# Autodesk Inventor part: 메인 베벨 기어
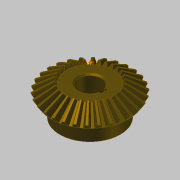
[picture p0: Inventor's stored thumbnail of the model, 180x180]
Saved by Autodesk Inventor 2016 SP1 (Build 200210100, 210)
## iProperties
Created: 2016-04
Part Number: 메인 베벨 기어
Material: 강철, 탄소
Document SubType Name: Modeling
Designer: mdu
Categories: <?xml version="1.0" encoding="UTF-16"?> <MemberInstance><Categories><FamilyTemplate><FamilyTemplateParameter ValueType="xs:double" Id="1" ObjectReferenceKey="da
Mass: 269.926 g
Surface Area: 108.837 cm^2
Volume: 34.2981 cm^3
Density: 7.87 g/cm^3
Appearance: 얼룩무늬
CustomPartVersion: 1
Author: mdu
Revision Number: 1
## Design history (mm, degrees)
node "맨 위 점"
node "메쉬 평면2"
sketch "톱니 본체 스케치"
  geometry: L1 (0, 0)-(28.669, -21.997); L2 (28.669, -21.997)-(31.109, -18.336); L3 (31.109, -18.336)-(0, 0); L4 (30, -20)-(0, 0); L5 (17.219, -13.212)-(18.685, -11.013); L6 (28.669, -21.997)-(17.219, -13.212); L7 (31.109, -18.336)-(18.685, -11.013); L8 (0, -39.387)-(0, 6.564) reference; L9 (0, -20)-(31.109, -20)
  constraints: 16 end point, 4 point on line, 3 perpendicular, 2 collinear, 1 horizontal alignment, 1 vertical alignment
  dimensions: "d0" = 60 diameter of L4.start L8 (= da_de); "d1" = 57.33744 diameter of L1.end L8 (= da_dfe); "d2" = 62.2188 diameter of L2.end L8 (= da_dae); "d3" = 14.4 distance between parallel lines of L2 L5 (= da_b); "d4" = 18.3359 vertical distance of L2.end L1.start (= da_ve)
revolve "톱니 본체" sketch "톱니 본체 스케치" stored, may be unused: angle "d5" = 90 deg
node "시작점"
node "톱니 평면"
sketch "시작 스케치"
  geometry: L1 (0, -23.505)-(0, 10.645) reference; L2 (-0.709, -2.928)-(0.709, -2.928); A1 r 19.188 centre (-19.457, -7.014) between (-0.709, -2.928) and (-3.232, 3.229); A2 r 19.188 centre (19.457, -7.014) between (3.232, 3.229) and (0.709, -2.928); A3 r 57.403 centre (0, -54.083) between (3.232, 3.229) and (-3.232, 3.229); 1 further point
  constraints: 6 point on circle, 3 centre point, 3 symmetric about line, 2 end point, 1 coincident, 1 perpendicular, 1 other
  dimensions: "d7" = 19.18795 radius of A1 (= fd_rr); "d8" = 19.45712 horizontal distance of point (0, -54.083) A1.centre (= fd_x); "d9" = 47.06905 vertical distance of point (0, -54.083) A1.centre (= fd_y); "d57" = 57.40327 radius of A3 (= 0.5 x fd_dva + 0.3 x da_he); "d58" = 51.15527 distance from line of A3.centre L2 (= 0.5 x fd_dva - 1.12 x da_he)
node "끝점"
  node "끝 평면"
sketch "3D 스케치 오른쪽"
  node "Helical Curve Right" dims "d65" = 229.90621 (computed from da_dm, da_delta, da_beta), "d66" = 31.5, "d67" = 60 (= da_de), "d68" = -9.82794 (= -da_delta), "d69" = 8.10972 (computed from fd_loft, da_delta)
node "끝 평면 오른쪽"
sketch "끝 스케치 오른쪽"
  geometry: L1 (0, -41.54)-(0, 13.178) reference; L2 (-0.422, -1.69)-(0.422, -1.69); A1 r 11.427 centre (-11.587, -4.123) between (-0.422, -1.69) and (-1.925, 1.977); A2 r 11.427 centre (11.587, -4.123) between (1.925, 1.977) and (0.422, -1.69); A3 r 34.184 centre (0, -32.153) between (1.925, 1.977) and (-1.925, 1.977); 1 further point
  constraints: 6 point on circle, 3 centre point, 3 symmetric about line, 2 end point, 1 coincident, 1 perpendicular, 1 other
  dimensions: "d70" = 11.58699 horizontal distance of A3.centre A1.centre (computed from fd_x, fd_ratio); "d71" = 28.03028 vertical distance of point (0, -32.153) A1.centre (computed from fd_y, fd_ratio); "d72" = 11.4267 radius of A1 (computed from fd_rr, fd_ratio); "d73" = 30.46369 distance from line of point (0, -32.153) L2 (computed from d58, fd_ratio); "d74" = 34.18446 radius of A3 (computed from d57, fd_ratio)
feature "로프트 오른쪽" sketch "끝 스케치 오른쪽" dims "d75" = 0, "d77" = 0, "d79" = 0, "d80" = 90 deg, "d85" = 20, "d92" = 90 deg, "d93" = 90 deg, "da_teethtype" = 0 [user parameter]
sketch "3D 스케치 왼쪽"
  node "Helical Curve Left" dims "d26" = 229.90621 (computed from da_dm, da_delta, da_beta), "d27" = 8.10972 (computed from fd_loft, da_delta), "d28" = 60 (= da_de), "d29" = -9.82794 (= -da_delta)
node "끝 평면 왼쪽"
sketch "끝 스케치 왼쪽" dims "d56" = 10.3728 (derived)
  geometry: L1 (0, -43.753)-(0, 15.405) reference; L2 (-0.422, -1.678)-(0.422, -1.678); A1 r 11.427 centre (-11.587, -4.111) between (-0.422, -1.678) and (-1.925, 1.988); A2 r 11.427 centre (11.587, -4.111) between (1.925, 1.988) and (0.422, -1.678); A3 r 34.184 centre (0, -32.142) between (1.925, 1.988) and (-1.925, 1.988); 2 further points; 1 other entity
  constraints: 6 point on circle, 3 centre point, 3 symmetric about line, 2 end point, 1 coincident, 2 other
  dimensions: "d30" = 11.4267 radius of A1 (computed from fd_rr, fd_ratio); "d31" = 11.58699 horizontal distance of point (0, -32.142) A1.centre (computed from fd_x, fd_ratio); "d32" = 28.03028 vertical distance of A1.centre point (0, -32.142) (computed from fd_y, fd_ratio); "d61" = 34.18446 radius of A3 (computed from d57, fd_ratio); "d62" = 30.46369 distance from line of point (0, -32.142) L2 (computed from d58, fd_ratio)
feature "로프트 왼쪽" sketch "끝 스케치 왼쪽" dims "d35" = 0, "d37" = 0, "d39" = 0, "d40" = 90 deg, "d84" = 10, "d90" = 90 deg, "d91" = 90 deg, "da_teethtype" = 0 [user parameter]
sketch "본체 스케치"
  geometry: L1 (0, -35.038)-(0, -19.531) reference; L2 (28.669, -21.997)-(17.219, -13.212) reference; L3 (17.219, -13.212)-(0, -13.212); L4 (28.669, -21.997)-(0, -21.997)
  constraints: 4 end point, 2 perpendicular, 2 point on line
revolve "본체 고정" sketch "본체 스케치" stored, may be unused: angle "d46" = 90 deg
feature "피치 지름" dims angle "d47" = 90 deg
sketch "스케치8"
  geometry: C1 r 22.5 at (0, 0); 1 further point
  constraints: 1 centre point, 1 coincident
  dimensions: "d94" = 45 diameter of C1
extrude "돌출1" join sketch "스케치8" distance "d95" = 13; taper "d96" = 0 deg
sketch "스케치9"
  geometry: 1 further point
hole "구멍1" sketch "스케치9" at (0, 0) diameter "d97" = 17; stored, may be unused: countersink angle "d101" = 90 deg, drill point angle "d103" = 118 deg; dims "d98" = 6, "d99" = 4, "d100" = 2, "d102" = 8
sketch "스케치10"
  geometry: L1 (8.124, 2.5)-(10.8, 2.5); L2 (10.8, 2.5)-(10.8, -2.5); L3 (10.8, -2.5)-(8.124, -2.5); A1 r 8.5 centre (0, 0) between (8.124, 2.5) and (8.124, -2.5) reference; 1 further point
  constraints: 6 end point, 2 parallel, 2 point on circle, 1 horizontal, 1 perpendicular
  dimensions: "d104" = 5 distance of L1.end L2.end; "d112" = 19.3 dimension on A1 L2
extrude "돌출2" cut sketch "스케치10" stored distance "d106" = 10; taper "d107" = 0 deg
chamfer "모따기1" distance "d108" = 1; stored, may be unused: second distance "d109" = 2, angle "d110" = 45 deg
fillet "모깎기1" dims "d111" = 2
body "Solid1"
feature "로프트" dims "d17" = 0, "d18" = 90 deg, "d19" = 0, "d20" = 90 deg, "d89" = 0, "da_teethtype" = 0 [user parameter]
pattern_circular "원형 패턴" dims angle "d22" = 360 deg, "d88" = 0, "da_teethtype" = 0 [user parameter]
pattern_circular "원형 패턴 오른쪽" dims angle "d82" = 360 deg, "da_teethtype" = 0 [user parameter]
pattern_circular "원형 패턴 왼쪽" dims angle "d42" = 360 deg, "da_teethtype" = 0 [user parameter]
sketch "끝 스케치"
  geometry: L1 (0, -15.359)-(0, 6.983) reference; L2 (-0.422, -1.69)-(0.422, -1.69); A1 r 11.427 centre (-11.587, -4.123) between (-0.422, -1.69) and (-1.925, 1.977); A2 r 11.427 centre (11.587, -4.123) between (1.925, 1.977) and (0.422, -1.69); A3 r 34.184 centre (0, -32.153) between (1.925, 1.977) and (-1.925, 1.977); 1 further point
  constraints: 6 point on circle, 3 centre point, 3 symmetric about line, 2 end point, 1 coincident, 1 other
  dimensions: "d12" = 11.4267 radius of A1 (computed from fd_rr, fd_ratio); "d15" = 11.58699 horizontal distance of A1.centre point (0, -32.153) (computed from fd_x, fd_ratio); "d16" = 28.03028 vertical distance of A1.centre point (0, -32.153) (computed from fd_y, fd_ratio); "d59" = 34.18446 radius of A3 (computed from d57, fd_ratio); "d60" = 30.46369 distance from line of A3.centre L2 (computed from d58, fd_ratio)
sketch "Sketch6"
  geometry: L1 (30, -20)-(0, 0) reference; L2 (0, -37.8)-(0, 6.3) reference
body "Srf1"
other parameters: "da_b" = 14.4 [user parameter; used in 2 equation terms], "da_de" = 60 [user parameter; used in 4 equation terms], "da_dae" = 62.2188 [user parameter; used in 2 equation terms], "da_dfe" = 57.33744 [user parameter; used in 1 equation term], "da_le" = 36.05551 [user parameter; used in 1 equation term], "da_omega" = 90 deg [user parameter; used in 1 equation term], "da_beta" = 0 [user parameter; used in 2 equation terms], "da_delta" = 9.82794 [user parameter; used in 8 equation terms], "da_alpha" = 20 deg [user parameter; used in 2 equation terms], "da_he" = 4.4 [user parameter; used in 4 equation terms], "da_ve" = 18.3359 [user parameter; used in 1 equation term], "fd_dv" = 108.16654 (computed from da_de, da_delta) [user parameter; used in 1 equation term], "fd_dva" = 112.16654 (computed from da_dae, da_delta) [user parameter; used in 3 equation terms], "fd_dvb" = 101.6433 (computed from fd_dv, da_alpha) [user parameter; used in 2 equation terms], "da_zv" = 540.83269 [user parameter; used in 1 equation term], "fd_loft" = 14.62 (= da_b + 0.05 x da_he) [user parameter; used in 4 equation terms], "fd_ratio" = 5.95514 (computed from da_le, fd_loft) [user parameter; used in 15 equation terms], "fd_rr" = 19.18795 (computed from fd_dd, fd_dvb) [user parameter; used in 6 equation terms], "fd_angle" = 0.29367 (computed from da_zv) [user parameter; used in 4 equation terms], "fd_x1" = 1.58802 (computed from da_dvw, fd_angle) [user parameter; used in 1 equation term], "fd_y1" = 54.05995 (computed from da_dvw, fd_angle) [user parameter; used in 1 equation term], "fd_x2" = 17.8691 (computed from fd_rr, fd_angle2, fd_angle) [user parameter; used in 1 equation term], "fd_y2" = 6.9909 (computed from fd_rr, fd_angle2, fd_angle) [user parameter; used in 1 equation term], "fd_x" = 19.45712 (= fd_x1 + fd_x2) [user parameter; used in 4 equation terms], "fd_y" = 47.06905 (= fd_y1 - fd_y2) [user parameter; used in 4 equation terms], "fd_angle2" = 3.43555 (computed from fd_dvb, fd_dd, da_alpha) [user parameter; used in 2 equation terms], "fd_dd" = 108.64654 (= fd_dva - 0.8 x da_he) [user parameter; used in 2 equation terms], "da_dvw" = 108.16654 [user parameter; used in 2 equation terms], "d11" = 14.62 (= fd_loft), "da_dm" = 48.01848 [user parameter; used in 2 equation terms], "da_x" = 0 [user parameter], "da_m" = 2 [user parameter], "d48" = 0, "d49" = 0, "d50" = 90 deg (= da_omega), "d51" = 6 deg (computed from da_z), "d52" = 0, "d53" = 0, "d54" = 0
